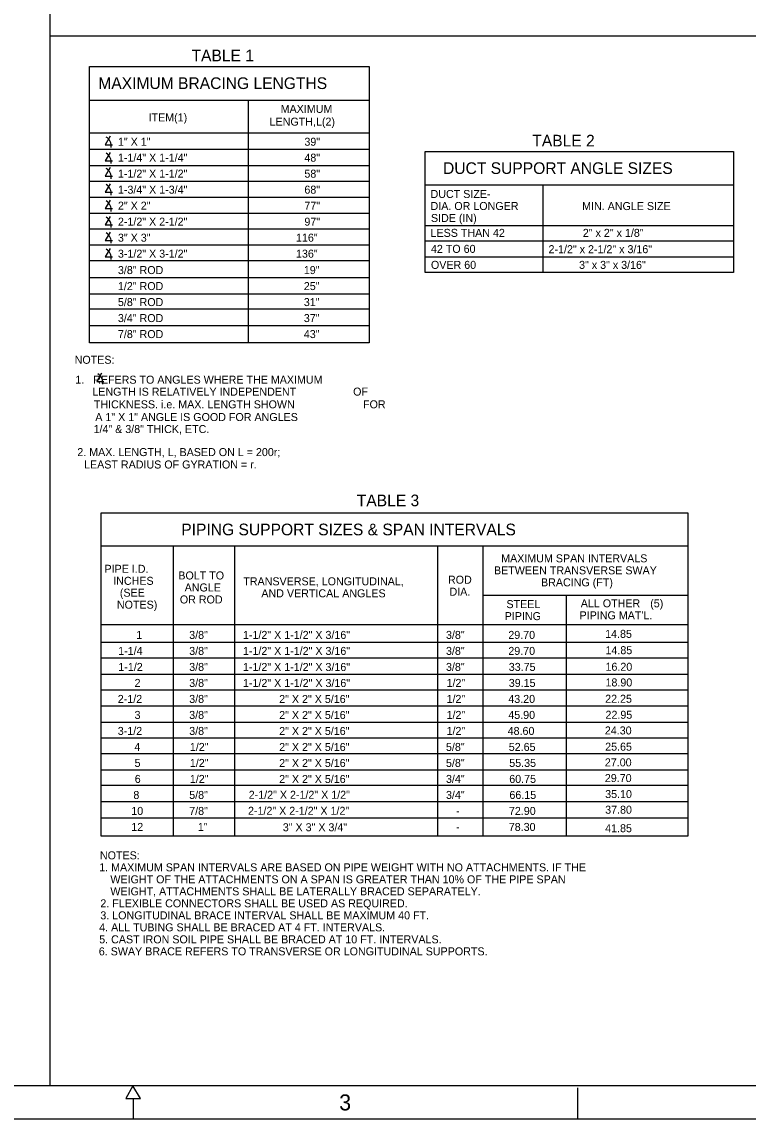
# Model space of a CAD drawing. Extents: x 10040.55 to 10045.84, y 10033.26 to 10035.76.
# Drawn here: x 10042.2 to 10043.108, y 10033.255 to 10034.627 of the extents above; entities that cross this region are included whole.
import ezdxf

# ---------------------------------------------------------------- set-up
doc = ezdxf.new("R2010")
doc.units = 0
doc.layers.add('Level 1', color=7, linetype='Continuous')
doc.layers.add('Level 2', color=7, linetype='Continuous')

msp = doc.modelspace()

# ---------------------------------------------------------------- linework, layer by layer
at = {"layer": 'Level 1'}
for p, q in [((10044.0053, 10033.2972), (10040.7136, 10033.2972)), ((10042.3386, 10033.2972), (10042.3295, 10033.2812)), ((10042.348, 10033.2812), (10042.3386, 10033.2972)), ((10042.8946, 10033.2555), (10042.8946, 10033.2945)), ((10042.3295, 10033.2812), (10042.348, 10033.2812)), ((10042.339, 10033.2812), (10042.339, 10033.2555)), ((10044.047, 10033.2555), (10040.547, 10033.2555))]:
    msp.add_line(p, q, dxfattribs=at)
at = {"layer": 'Level 2'}
for p, q in [((10042.2348, 10035.7139), (10042.2348, 10033.2972)), ((10042.2348, 10034.6093), (10044.0053, 10034.6093)), ((10042.2843, 10034.5709), (10042.6337, 10034.5709)), ((10042.2843, 10034.2255), (10042.2843, 10034.5709)), ((10042.6337, 10034.5709), (10042.6337, 10034.2255)), ((10042.2846, 10034.5291), (10042.6337, 10034.5291)), ((10042.4827, 10034.5291), (10042.4827, 10034.2255)), ((10042.2846, 10034.488), (10042.6337, 10034.488)), ((10042.31, 10034.4838), (10042.3039, 10034.4733)), ((10042.3039, 10034.4733), (10042.3129, 10034.4733)), ((10042.2845, 10034.4676), (10042.6337, 10034.4676)), ((10042.31, 10034.4635), (10042.3039, 10034.453)), ((10042.2845, 10034.4475), (10042.6337, 10034.4475)), ((10042.3039, 10034.453), (10042.3129, 10034.453)), ((10042.31, 10034.4446), (10042.3039, 10034.4341)), ((10042.3039, 10034.4341), (10042.3129, 10034.4341)), ((10042.2845, 10034.4279), (10042.6337, 10034.4279)), ((10042.31, 10034.4243), (10042.3039, 10034.4138)), ((10042.7039, 10034.4232), (10043.0893, 10034.4232)), ((10042.8511, 10034.4232), (10042.8511, 10034.3135)), ((10042.2845, 10034.4078), (10042.6337, 10034.4078)), ((10042.3039, 10034.4138), (10042.3129, 10034.4138)), ((10042.31, 10034.4039), (10042.3039, 10034.3934)), ((10042.3039, 10034.3934), (10042.3129, 10034.3934)), ((10042.2845, 10034.3877), (10042.6337, 10034.3877)), ((10042.31, 10034.3836), (10042.3039, 10034.3731)), ((10042.2845, 10034.3681), (10042.6337, 10034.3681)), ((10042.3039, 10034.3731), (10042.3129, 10034.3731)), ((10042.31, 10034.364), (10042.3039, 10034.3535)), ((10042.7039, 10034.3722), (10043.0893, 10034.3722)), ((10042.2845, 10034.348), (10042.6337, 10034.348)), ((10042.3039, 10034.3535), (10042.3129, 10034.3535)), ((10042.7039, 10034.3531), (10043.0893, 10034.3531)), ((10042.31, 10034.3436), (10042.3039, 10034.3332)), ((10042.2845, 10034.3284), (10042.6337, 10034.3284)), ((10042.3039, 10034.3332), (10042.3129, 10034.3332)), ((10042.7039, 10034.3333), (10043.0893, 10034.3333)), ((10042.2847, 10034.3074), (10042.6337, 10034.3074)), ((10042.2847, 10034.2871), (10042.6337, 10034.2871)), ((10042.2844, 10034.268), (10042.6337, 10034.268)), ((10042.2847, 10034.2474), (10042.6337, 10034.2474)), ((10042.6337, 10034.2255), (10042.2843, 10034.2255)), ((10042.2994, 10034.1877), (10042.2934, 10034.1772)), ((10042.2934, 10034.1772), (10042.3023, 10034.1772)), ((10042.2988, 10034.0133), (10043.0323, 10034.0133)), ((10042.2988, 10033.6092), (10042.2988, 10034.0133)), ((10043.0323, 10034.0133), (10043.0323, 10033.6092)), ((10043.0323, 10033.9714), (10042.2988, 10033.9714)), ((10042.389, 10033.9714), (10042.389, 10033.6089)), ((10042.4654, 10033.9714), (10042.4654, 10033.6089)), ((10042.7195, 10033.9714), (10042.7195, 10033.6089)), ((10042.776, 10033.9714), (10042.776, 10033.6092)), ((10042.7764, 10033.9102), (10043.0323, 10033.9102)), ((10042.8803, 10033.9102), (10042.8803, 10033.6092)), ((10042.2988, 10033.8735), (10043.0323, 10033.8735)), ((10042.2988, 10033.8515), (10043.0323, 10033.8515)), ((10042.2988, 10033.8318), (10043.0323, 10033.8318)), ((10042.2988, 10033.8117), (10043.0323, 10033.8117)), ((10042.2988, 10033.7919), (10043.0323, 10033.7919)), ((10042.2988, 10033.7718), (10043.0323, 10033.7718)), ((10042.2988, 10033.7514), (10043.0323, 10033.7514)), ((10042.2988, 10033.732), (10043.0323, 10033.732)), ((10042.2988, 10033.7122), (10043.0323, 10033.7122)), ((10042.2988, 10033.6919), (10043.0323, 10033.6919)), ((10042.2988, 10033.6726), (10043.0323, 10033.6726)), ((10042.2988, 10033.6524), (10043.0323, 10033.6524)), ((10042.2988, 10033.6321), (10043.0323, 10033.6321)), ((10043.0323, 10033.6092), (10042.2988, 10033.6092))]:
    msp.add_line(p, q, dxfattribs=at)
msp.add_lwpolyline([(10042.7039, 10034.3135), (10042.7039, 10034.4647), (10043.0893, 10034.4647), (10043.0893, 10034.3135)], close=True, dxfattribs=at)
for centre in [(10042.2985, 10034.4718), (10042.2985, 10034.4515), (10042.2985, 10034.4326), (10042.2985, 10034.4123), (10042.2985, 10034.3919), (10042.2985, 10034.3716), (10042.2985, 10034.352), (10042.2985, 10034.3317), (10042.288, 10034.1757)]:
    msp.add_arc(centre, 0.0129, 351.5535, 59.0793, dxfattribs=at)

# ---------------------------------------------------------------- texts
at = {"layer": 'Level 1'}
msp.add_text('3', height=0.02, dxfattribs=at).set_placement((10042.5964, 10033.2663))
at = {"layer": 'Level 2'}
for s, height, p in [('TABLE 1', 0.01458, (10042.4118, 10034.5775)), ('MAXIMUM BRACING LENGTHS', 0.014583, (10042.2953, 10034.5429)), ('ITEM(1)', 0.01, (10042.3581, 10034.5024)), ('MAXIMUM', 0.01, (10042.5232, 10034.5131)), ('LENGTH,L(2)', 0.01, (10042.5094, 10034.4971)), ('TABLE 2', 0.01458, (10042.8378, 10034.4711)), ('1" X 1"', 0.01, (10042.3198, 10034.472)), ('39"', 0.01, (10042.5529, 10034.472)), ('1-1/4" X 1-1/4"', 0.01, (10042.3198, 10034.4521)), ('48"', 0.01, (10042.5529, 10034.4521)), ('DUCT SUPPORT ANGLE SIZES', 0.014583, (10042.7262, 10034.4367)), ('1-1/2" X 1-1/2"', 0.01, (10042.3198, 10034.4321)), ('58"', 0.01, (10042.5529, 10034.4321)), ('1-3/4" X 1-3/4"', 0.01, (10042.3198, 10034.4121)), ('68"', 0.01, (10042.5529, 10034.4121)), ('DUCT SIZE-', 0.01, (10042.7106, 10034.4067)), ('2" X 2"', 0.01, (10042.3198, 10034.3921)), ('77"', 0.01, (10042.5529, 10034.3921)), ('DIA. OR LONGER', 0.01, (10042.7106, 10034.3917)), ('MIN. ANGLE SIZE', 0.01, (10042.9001, 10034.3916)), ('2-1/2" X 2-1/2"', 0.01, (10042.3198, 10034.3721)), ('97"', 0.01, (10042.5529, 10034.3721)), ('SIDE (IN)', 0.01, (10042.7111, 10034.3767)), ('3" X 3"', 0.01, (10042.3198, 10034.3521)), ('116"', 0.01, (10042.5424, 10034.3521)), ('LESS THAN 42', 0.01, (10042.7106, 10034.3581)), ('2" x 2" x 1/8"', 0.01, (10042.901, 10034.3581)), ('42 TO 60', 0.01, (10042.7111, 10034.3381)), ('2-1/2" x 2-1/2" x 3/16"', 0.01, (10042.8581, 10034.3377)), ('3-1/2" X 3-1/2"', 0.01, (10042.3198, 10034.3321)), ('136"', 0.01, (10042.5424, 10034.3321)), ('3/8" ROD', 0.01, (10042.3198, 10034.3116)), ('19"', 0.01, (10042.5522, 10034.3116)), ('OVER 60', 0.01, (10042.7111, 10034.3181)), ('3" x 3" x 3/16"', 0.01, (10042.8963, 10034.3181)), ('1/2" ROD', 0.01, (10042.3198, 10034.2916)), ('25"', 0.01, (10042.5522, 10034.2916)), ('5/8" ROD', 0.01, (10042.3198, 10034.2716)), ('31"', 0.01, (10042.5522, 10034.2716)), ('3/4" ROD', 0.01, (10042.3198, 10034.2516)), ('37"', 0.01, (10042.5522, 10034.2516)), ('7/8" ROD', 0.01, (10042.3198, 10034.2316)), ('43"', 0.01, (10042.5522, 10034.2316)), ('NOTES:', 0.01, (10042.2657, 10034.1995)), ('1.   REFERS TO ANGLES WHERE THE MAXIMUM', 0.01, (10042.2665, 10034.1746)), ('LENGTH IS RELATIVELY INDEPENDENT', 0.01, (10042.2878, 10034.1596)), ('OF', 0.01, (10042.6138, 10034.1597)), ('THICKNESS. i.e. MAX. LENGTH SHOWN', 0.01, (10042.2897, 10034.1438)), ('FOR', 0.01, (10042.6262, 10034.1438)), ('A 1" X 1" ANGLE IS GOOD FOR ANGLES', 0.01, (10042.2915, 10034.1279)), ('1/4" & 3/8" THICK, ETC.', 0.01, (10042.2893, 10034.1129)), ('2. MAX. LENGTH, L, BASED ON L = 200r; ', 0.01, (10042.269, 10034.0841)), ('   LEAST RADIUS OF GYRATION = r.', 0.01, (10042.2663, 10034.0686)), ('TABLE 3', 0.01458, (10042.6184, 10034.0214)), ('PIPING SUPPORT SIZES & SPAN INTERVALS', 0.014583, (10042.399, 10033.9851)), ('MAXIMUM SPAN INTERVALS', 0.01, (10042.7989, 10033.9513)), ('PIPE I.D.', 0.01, (10042.303, 10033.9382)), ('BOLT TO', 0.01, (10042.3953, 10033.9299)), ('BETWEEN TRANSVERSE SWAY', 0.01, (10042.7899, 10033.9363)), ('INCHES', 0.01, (10042.3139, 10033.9232)), ('ANGLE', 0.01, (10042.4032, 10033.9149)), ('TRANSVERSE, LONGITUDINAL,', 0.01, (10042.4765, 10033.9226)), ('ROD', 0.01, (10042.7324, 10033.9246)), ('BRACING (FT)', 0.01, (10042.8487, 10033.9213)), ('(SEE', 0.01, (10042.3222, 10033.9084)), ('OR ROD', 0.01, (10042.3972, 10033.8999)), ('AND VERTICAL ANGLES', 0.01, (10042.4991, 10033.9076)), ('DIA.', 0.01, (10042.7343, 10033.9096)), ('NOTES)', 0.01, (10042.3185, 10033.8934)), ('STEEL', 0.01, (10042.8055, 10033.8941)), ('ALL OTHER', 0.01, (10042.8984, 10033.8951)), ('(5)', 0.01, (10042.9852, 10033.8951)), ('PIPING', 0.01, (10042.8033, 10033.8791)), ("PIPING MAT'L.", 0.01, (10042.8969, 10033.8801)), ('1', 0.01, (10042.3427, 10033.8556)), ('3/8"', 0.01, (10042.4089, 10033.8556)), ('1-1/2" X 1-1/2" X 3/16"', 0.01, (10042.4761, 10033.8556)), ('3/8"', 0.01, (10042.7299, 10033.8556)), ('29.70', 0.01, (10042.8078, 10033.8556)), ('14.85', 0.01, (10042.9289, 10033.8569)), ('1-1/4', 0.01, (10042.3201, 10033.8356)), ('3/8"', 0.01, (10042.4089, 10033.8356)), ('1-1/2" X 1-1/2" X 3/16"', 0.01, (10042.4761, 10033.8356)), ('3/8"', 0.01, (10042.7299, 10033.8356)), ('29.70', 0.01, (10042.8078, 10033.8356)), ('14.85', 0.01, (10042.9293, 10033.8365)), ('1-1/2', 0.01, (10042.3203, 10033.8156)), ('3/8"', 0.01, (10042.4089, 10033.8156)), ('1-1/2" X 1-1/2" X 3/16"', 0.01, (10042.4761, 10033.8155)), ('3/8"', 0.01, (10042.7299, 10033.8156)), ('33.75', 0.01, (10042.8084, 10033.8156)), ('16.20', 0.01, (10042.9293, 10033.8158)), ('2', 0.01, (10042.3406, 10033.7956)), ('3/8"', 0.01, (10042.4089, 10033.7956)), ('1-1/2" X 1-1/2" X 3/16"', 0.01, (10042.4761, 10033.7955)), ('1/2"', 0.01, (10042.7306, 10033.7956)), ('39.15', 0.01, (10042.8084, 10033.7956)), ('18.90', 0.01, (10042.9293, 10033.7962)), ('2-1/2', 0.01, (10042.3196, 10033.7756)), ('3/8"', 0.01, (10042.4089, 10033.7756)), ('2" X 2" X 5/16"', 0.01, (10042.5214, 10033.7755)), ('1/2"', 0.01, (10042.7306, 10033.7756)), ('43.20', 0.01, (10042.8078, 10033.7756)), ('22.25', 0.01, (10042.9289, 10033.7758)), ('3', 0.01, (10042.3406, 10033.7556)), ('3/8"', 0.01, (10042.4089, 10033.7556)), ('2" X 2" X 5/16"', 0.01, (10042.5214, 10033.7555)), ('1/2"', 0.01, (10042.7306, 10033.7556)), ('45.90', 0.01, (10042.8078, 10033.7556)), ('22.95', 0.01, (10042.9293, 10033.7558)), ('3-1/2', 0.01, (10042.3196, 10033.7356)), ('3/8"', 0.01, (10042.4089, 10033.7356)), ('2" X 2" X 5/16"', 0.01, (10042.5214, 10033.7355)), ('1/2"', 0.01, (10042.7306, 10033.7356)), ('48.60', 0.01, (10042.807, 10033.7356)), ('24.30', 0.01, (10042.9285, 10033.7362)), ('4', 0.01, (10042.3403, 10033.7156)), ('1/2"', 0.01, (10042.4097, 10033.7156)), ('2" X 2" X 5/16"', 0.01, (10042.5214, 10033.7155)), ('5/8"', 0.01, (10042.7299, 10033.7156)), ('52.65', 0.01, (10042.8084, 10033.7156)), ('25.65', 0.01, (10042.9289, 10033.7159)), ('5', 0.01, (10042.3406, 10033.6956)), ('1/2"', 0.01, (10042.4097, 10033.6956)), ('2" X 2" X 5/16"', 0.01, (10042.5214, 10033.6955)), ('5/8"', 0.01, (10042.7299, 10033.6956)), ('55.35', 0.01, (10042.809, 10033.6956)), ('27.00', 0.01, (10042.9285, 10033.6963)), ('6', 0.01, (10042.3408, 10033.6756)), ('1/2"', 0.01, (10042.4097, 10033.6756)), ('2" X 2" X 5/16"', 0.01, (10042.5214, 10033.6755)), ('3/4"', 0.01, (10042.7299, 10033.6756)), ('60.75', 0.01, (10042.809, 10033.6756)), ('29.70', 0.01, (10042.9285, 10033.6767)), ('8', 0.01, (10042.3391, 10033.6556)), ('5/8"', 0.01, (10042.4089, 10033.6556)), ('2-1/2" X 2-1/2" X 1/2"', 0.01, (10042.4833, 10033.6558)), ('3/4"', 0.01, (10042.7299, 10033.6556)), ('66.15', 0.01, (10042.8092, 10033.6556)), ('35.10', 0.01, (10042.9289, 10033.6567)), ('10', 0.01, (10042.3365, 10033.6356)), ('7/8"', 0.01, (10042.4089, 10033.6356)), ('2-1/2" X 2-1/2" X 1/2"', 0.01, (10042.4824, 10033.6358)), ('-', 0.01, (10042.7425, 10033.6356)), ('72.90', 0.01, (10042.8086, 10033.6356)), ('37.80', 0.01, (10042.9289, 10033.6371)), ('12', 0.01, (10042.3365, 10033.6156)), ('1"', 0.01, (10042.4197, 10033.6156)), ('3" X 3" X 3/4"', 0.01, (10042.5259, 10033.6152)), ('78.30', 0.01, (10042.8084, 10033.6156)), ('41.85', 0.01, (10042.9289, 10033.614)), ('-', 0.01, (10042.7425, 10033.6156)), ('NOTES:', 0.01, (10042.2973, 10033.5801)), ('1. MAXIMUM SPAN INTERVALS ARE BASED ON PIPE WEIGHT WITH NO ATTACHMENTS. IF THE', 0.01, (10042.2964, 10033.5651)), ('   WEIGHT OF THE ATTACHMENTS ON A SPAN IS GREATER THAN 10% OF THE PIPE SPAN', 0.01, (10042.2992, 10033.5501)), ('   WEIGHT, ATTACHMENTS SHALL BE LATERALLY BRACED SEPARATELY.', 0.01, (10042.2992, 10033.5351)), ('2. FLEXIBLE CONNECTORS SHALL BE USED AS REQUIRED.', 0.01, (10042.2978, 10033.5201)), ('3. LONGITUDINAL BRACE INTERVAL SHALL BE MAXIMUM 40 FT.', 0.01, (10042.2978, 10033.5051)), ('4. ALL TUBING SHALL BE BRACED AT 4 FT. INTERVALS.', 0.01, (10042.2964, 10033.4901)), ('5. CAST IRON SOIL PIPE SHALL BE BRACED AT 10 FT. INTERVALS.', 0.01, (10042.2964, 10033.4751)), ('6. SWAY BRACE REFERS TO TRANSVERSE OR LONGITUDINAL SUPPORTS.', 0.01, (10042.2959, 10033.4601))]:
    msp.add_text(s, height=height, dxfattribs=at).set_placement(p)

doc.saveas('drawing.dxf')
